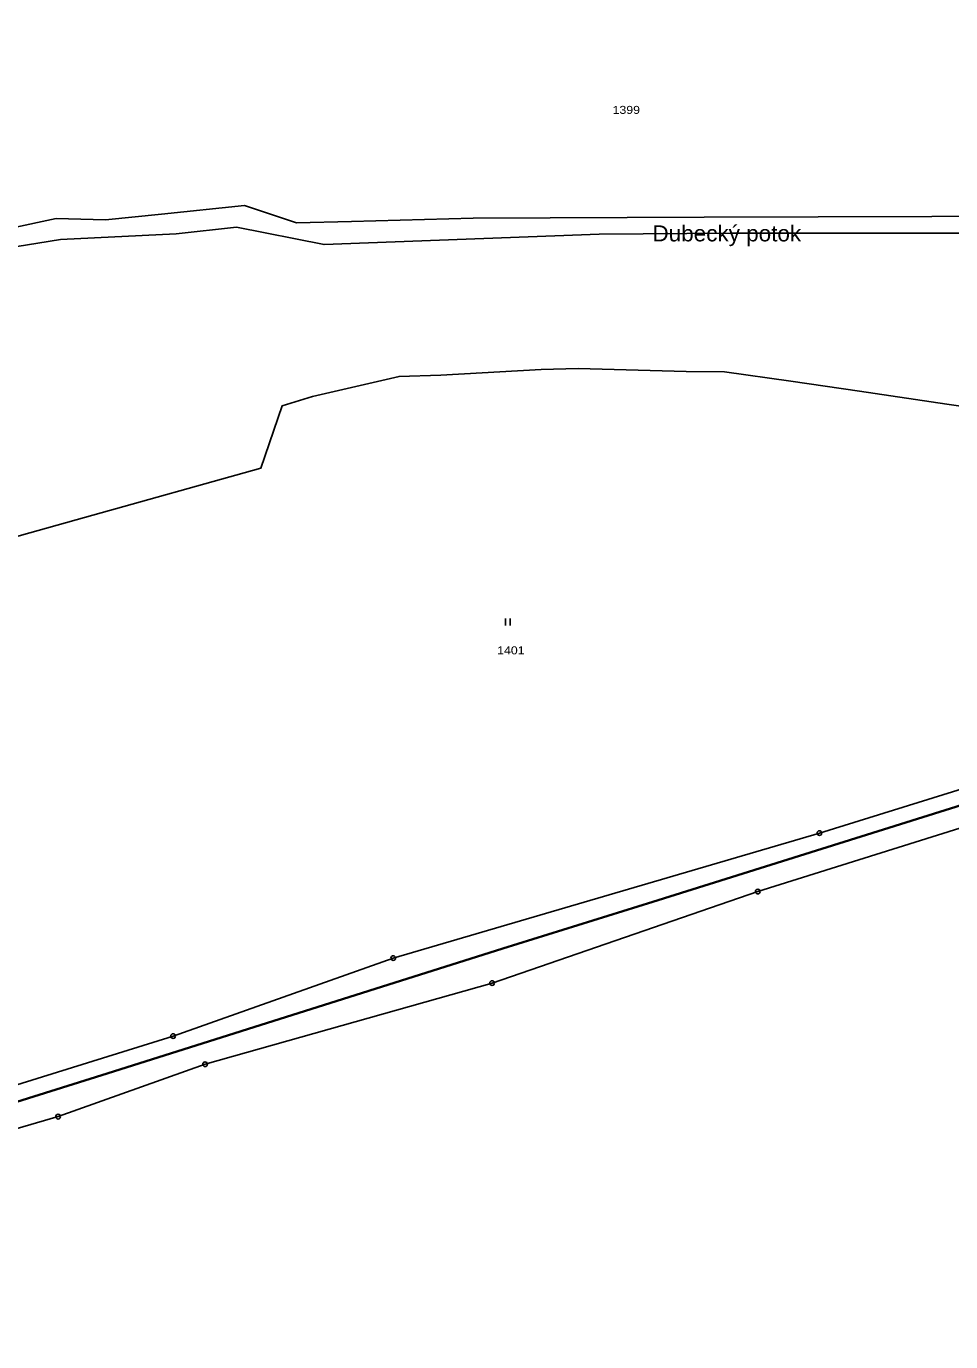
# Model space of a CAD drawing. Extents: x -872229 to -869198, y -1075981 to -1074329.
# Drawn here: x -870236.3 to -870040, y -1075493.1 to -1075213.8 of the extents above; entities that cross this region are included whole.
import ezdxf
from ezdxf.enums import TextEntityAlignment as Align

# ---------------------------------------------------------------- set-up
doc = ezdxf.new("R2010")
doc.units = 0
doc.header["$LTSCALE"] = 0.68
for name, color, linetype, lineweight in [('1', 7, 'Continuous', 25), ('3', 7, 'Continuous', 25), ('6', 7, 'Continuous', 25), ('7', 7, 'Continuous', 13), ('8', 7, 'Continuous', 25)]:
    doc.layers.add(name, color=color, linetype=linetype, lineweight=lineweight)
doc.layers.add('2', color=7, linetype='Continuous')

msp = doc.modelspace()

# ---------------------------------------------------------------- linework, layer by layer
at = {"layer": '1'}
for points in [[(-870385.12, -1075316.07), (-870355.23, -1075301.89), (-870314.21, -1075282.93), (-870280.58, -1075266.36), (-870265.86, -1075261.9), (-870249.15, -1075258.69), (-870230, -1075254.57), (-870219.5, -1075254.87), (-870207.6, -1075253.65), (-870190, -1075251.81), (-870178.96, -1075255.5), (-870167.23, -1075255.17), (-870141.46, -1075254.46), (-870092.41, -1075254.3), (-870019.81, -1075254.06), (-869952.16, -1075254.08), (-869902.23, -1075254.21), (-869809.43, -1075253.56), (-869784.98, -1075249.67), (-869765.49, -1075244.15), (-869696.7, -1075225.43), (-869659.27, -1075213.75)], [(-870389.39, -1075322.98), (-870381.24, -1075318.31), (-870366.64, -1075311.61), (-870346.71, -1075301.64), (-870331.27, -1075294.54), (-870292.97, -1075277.13), (-870277.78, -1075269.99), (-870255.58, -1075264.06), (-870240.85, -1075260.92), (-870229.06, -1075259.04), (-870204.53, -1075257.8), (-870191.67, -1075256.42), (-870173.08, -1075260.11), (-870114.64, -1075257.88), (-870086.74, -1075257.68), (-870033.35, -1075257.7)], [(-870249.5, -1075325.23), (-870223.98, -1075318.04), (-870186.49, -1075307.57), (-870182, -1075294.31), (-870175.53, -1075292.39), (-870157.15, -1075288.1), (-870148.32, -1075287.84), (-870126.97, -1075286.65), (-870119.12, -1075286.39), (-870096.19, -1075287.05), (-870088.07, -1075287.11), (-870073.97, -1075289.09), (-870059.41, -1075291.2), (-870040.81, -1075293.97), (-870019.39, -1075297.01)], [(-869861.67, -1075370.56), (-869878.14, -1075367.33), (-869908.77, -1075363.47), (-869918.42, -1075363.79), (-869963.81, -1075365.31), (-869991.44, -1075371.29), (-870013.06, -1075376.14), (-870080.98, -1075397.47), (-870137.41, -1075416.91), (-870198.36, -1075434.14), (-870229.56, -1075445.28), (-870312.6, -1075469.56), (-870365.19, -1075486.42), (-870398.17, -1075493.93), (-870445.72, -1075497.57), (-870473.49, -1075498.03), (-870483.95, -1075496.85)], [(-870486.5, -1075484.99), (-870484.52, -1075485.24), (-870480.75, -1075482.95), (-870462.19, -1075488.41), (-870441.81, -1075489.8), (-870382.34, -1075482.14), (-870362.98, -1075477.23), (-870347.8, -1075472.63), (-870325.84, -1075466.04), (-870298.48, -1075457.59), (-870279.74, -1075451.72), (-870275.31, -1075449.42), (-870268.89, -1075443.67), (-870252.29, -1075442.86), (-870205.14, -1075428.17), (-870158.39, -1075411.62), (-870067.91, -1075385.07), (-870005.01, -1075365.55)]]:
    msp.add_lwpolyline(points, dxfattribs=at)
at = {"layer": '3'}
for p, q in [((-870134.551, -1075341.02), (-870134.551, -1075339.52)), ((-870133.55, -1075341.02), (-870133.55, -1075339.52))]:
    msp.add_line(p, q, dxfattribs=at)
at = {"layer": '6', "lineweight": 35}
msp.add_line((-870135.1, -1075409.54), (-870103.28, -1075399.64), dxfattribs=at)
for points in [[(-870103.28, -1075399.64), (-870067.42, -1075388.4), (-870019.78, -1075373.46)], [(-870252.84, -1075446.64), (-870219.18, -1075436.13), (-870135.1, -1075409.54)]]:
    msp.add_lwpolyline(points, dxfattribs=at)
at = {"layer": '8'}
for centre, radius in [((-870067.91, -1075385.0699), 0.5), ((-870067.91, -1075385.0699), 0.0303), ((-870080.98, -1075397.4699), 0.5), ((-870080.98, -1075397.4699), 0.0303), ((-870158.39, -1075411.6199), 0.5), ((-870158.39, -1075411.6199), 0.0303), ((-870137.41, -1075416.9099), 0.5), ((-870137.41, -1075416.9099), 0.0303), ((-870205.14, -1075428.1699), 0.5), ((-870205.14, -1075428.1699), 0.0303), ((-870198.36, -1075434.1399), 0.5), ((-870198.36, -1075434.1399), 0.0303), ((-870229.56, -1075445.2799), 0.5), ((-870229.56, -1075445.2799), 0.0303)]:
    msp.add_circle(centre, radius, dxfattribs=at)

# ---------------------------------------------------------------- texts
at = {"layer": '2', "width": 1.15}
for s, p in [('1399', (-870111.82, -1075232.35)), ('1401', (-870136.33, -1075347.11))]:
    msp.add_text(s, height=1.7, dxfattribs=at).set_placement(p)
at = {"layer": '7', "width": 1.05}
msp.add_text('Dubecký potok', height=3.4, dxfattribs=at).set_placement((-870087.569, -1075259.42), align=Align.CENTER)

doc.saveas('drawing.dxf')
